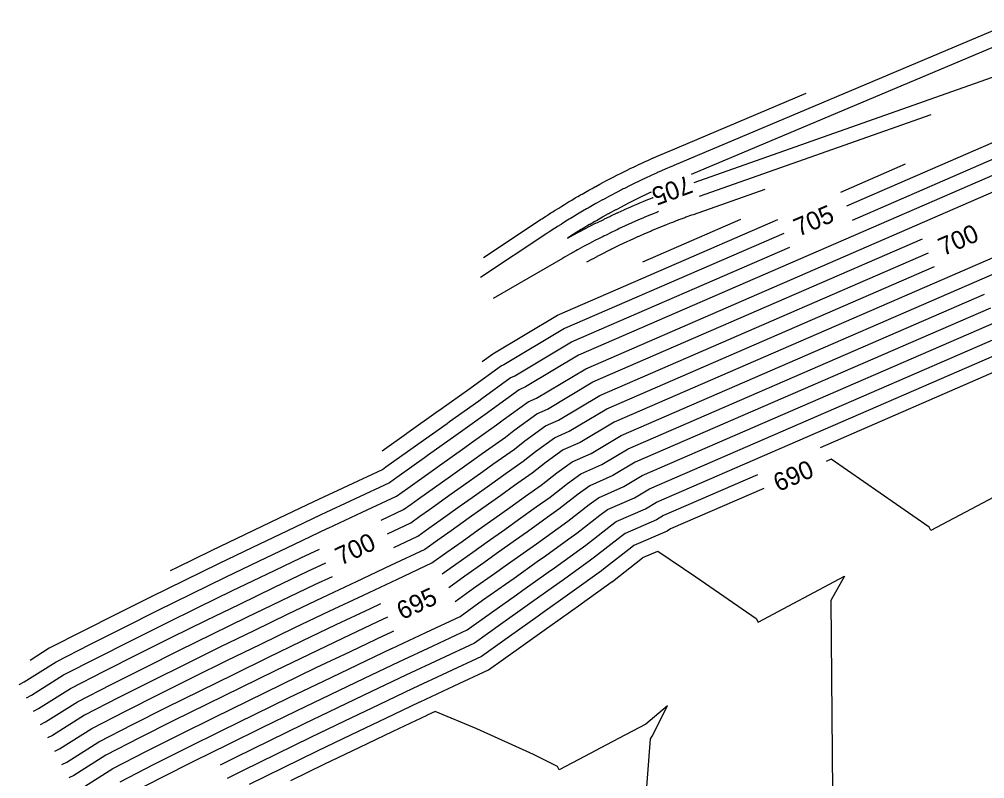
# Model space of a CAD drawing. Extents: x 1487507 to 1489130, y 497211 to 499439.
# Drawn here: x 1487812.8 to 1487940.5, y 498440 to 498540.5 of the extents above; entities that cross this region are included whole.
import ezdxf

# ---------------------------------------------------------------- set-up
doc = ezdxf.new("R2010")
doc.units = 0
for name, color, linetype in [('Prop CMT Ditch DDE', 7, 'Continuous'), ('Prop Drainage Ditch Flow Line', 7, 'Continuous'), ('Prop Drainage Structure Box Number Symbol CELL', 7, 'Continuous'), ('Prop Drainage Structure Pipe Outlet Channel Detail CELL', 7, 'Continuous')]:
    doc.layers.add(name, color=color, linetype=linetype)

msp = doc.modelspace()

# ---------------------------------------------------------------- linework, layer by layer
at = {"layer": 'Prop CMT Ditch DDE'}
for points in [[(1487945.21, 498540.46), (1487899.4, 498521.12), (1487899.22, 498521.05), (1487899.2, 498521.04), (1487899.1, 498520.99), (1487898.26, 498520.63), (1487898.16, 498520.59), (1487897.45, 498520.28), (1487897.44, 498520.27), (1487897.32, 498520.22), (1487897.2, 498520.16), (1487896.39, 498519.79), (1487895.65, 498519.45), (1487895.53, 498519.39), (1487895.46, 498519.36), (1487895.32, 498519.3), (1487894.53, 498518.92), (1487894.39, 498518.85), (1487893.62, 498518.47), (1487893.62, 498518.47), (1487892.86, 498518.09), (1487892.7, 498518.01), (1487892.54, 498517.92), (1487891.79, 498517.54), (1487891.73, 498517.51), (1487891.05, 498517.15), (1487890.89, 498517.06), (1487890.18, 498516.68), (1487889.99, 498516.58), (1487889.96, 498516.56), (1487889.86, 498516.51), (1487889.26, 498516.17), (1487889.09, 498516.08), (1487888.41, 498515.69), (1487888.2, 498515.58), (1487888.06, 498515.49), (1487888.02, 498515.47), (1487887.85, 498515.37), (1487887.32, 498515.06), (1487886.66, 498514.67), (1487886.44, 498514.54), (1487886.38, 498514.5), (1487886.19, 498514.39), (1487885.73, 498514.11), (1487885.57, 498514.01), (1487885.34, 498513.87), (1487884.7, 498513.47), (1487884.48, 498513.33), (1487884.4, 498513.28), (1487884, 498513.03), (1487883.84, 498512.93), (1487883.6, 498512.76), (1487882.99, 498512.37), (1487882.73, 498512.2), (1487882.62, 498512.13), (1487873.81, 498506.28)], [(1487874.23, 498508.96), (1487881.57, 498513.83), (1487881.77, 498513.96), (1487881.94, 498514.07), (1487882.41, 498514.38), (1487882.81, 498514.64), (1487883.12, 498514.84), (1487883.38, 498515), (1487883.55, 498515.11), (1487883.69, 498515.2), (1487884.17, 498515.49), (1487884.57, 498515.75), (1487884.92, 498515.95), (1487885.21, 498516.13), (1487885.33, 498516.2), (1487885.46, 498516.29), (1487885.89, 498516.54), (1487886.36, 498516.82), (1487886.71, 498517.02), (1487887.07, 498517.23), (1487887.16, 498517.28), (1487887.26, 498517.34), (1487887.73, 498517.61), (1487888.17, 498517.85), (1487888.59, 498518.09), (1487888.95, 498518.29), (1487889.02, 498518.33), (1487889.08, 498518.36), (1487889.6, 498518.64), (1487890, 498518.85), (1487890.5, 498519.12), (1487890.85, 498519.31), (1487890.92, 498519.34), (1487891.47, 498519.63), (1487891.85, 498519.82), (1487892.42, 498520.1), (1487892.78, 498520.29), (1487892.78, 498520.29), (1487893.13, 498520.46), (1487893.72, 498520.75), (1487894.06, 498520.91), (1487894.66, 498521.19), (1487894.73, 498521.23), (1487895.05, 498521.38), (1487895.6, 498521.64), (1487895.95, 498521.79), (1487896.56, 498522.07), (1487896.61, 498522.09), (1487896.69, 498522.13), (1487896.99, 498522.26), (1487897.51, 498522.49), (1487897.85, 498522.63), (1487898.47, 498522.9), (1487898.55, 498522.93), (1487898.68, 498522.99), (1487916.89, 498530.68)], [(1487933.36, 498527.82), (1487902.76, 498517.01)], [(1487923, 498513.9), (1487950.27, 498525.73)], [(1487951.2, 498523.97), (1487886.8, 498496), (1487879.8, 498491.81), (1487878.94, 498491.44), (1487875.42, 498488.88), (1487874.77, 498488.37), (1487871.18, 498485.83), (1487870.58, 498485.41), (1487866.97, 498482.84), (1487866.42, 498482.45), (1487862.77, 498479.83), (1487862.27, 498479.48), (1487861.79, 498479.13), (1487857.26, 498477), (1487852.73, 498474.88), (1487852.72, 498474.88), (1487848.2, 498472.74), (1487843.69, 498470.57), (1487839.18, 498468.4), (1487834.69, 498466.2), (1487830.2, 498463.99), (1487825.72, 498461.76), (1487821.26, 498459.52), (1487816.81, 498457.23), (1487814.29, 498455.63)], [(1487812.85, 498452.44), (1487813.51, 498452.78), (1487817.74, 498455.46), (1487822.19, 498457.75), (1487826.66, 498459.99), (1487831.14, 498462.22), (1487835.62, 498464.44), (1487840.12, 498466.63), (1487844.62, 498468.81), (1487849.14, 498470.97), (1487853.66, 498473.11), (1487853.67, 498473.12), (1487858.19, 498475.24), (1487862.72, 498477.36), (1487863.46, 498477.89), (1487864.2, 498478.42), (1487867.61, 498480.86), (1487868.41, 498481.42), (1487871.77, 498483.81), (1487872.61, 498484.42), (1487875.95, 498486.78), (1487876.84, 498487.47), (1487880.11, 498489.85), (1487881.24, 498490.35), (1487887.74, 498494.23), (1487952.14, 498522.2)], [(1487929.99, 498521.28), (1487921.41, 498517.55)], [(1487911.41, 498517.94), (1487901.93, 498514.59), (1487901.77, 498514.54), (1487901.74, 498514.53), (1487900.99, 498514.26), (1487900.84, 498514.2), (1487900.2, 498513.97), (1487900.07, 498513.92), (1487899.96, 498513.88), (1487899.94, 498513.87), (1487899.2, 498513.58), (1487899.05, 498513.53), (1487898.36, 498513.26), (1487898.22, 498513.2), (1487898.16, 498513.18), (1487897.41, 498512.88), (1487897.27, 498512.82), (1487896.53, 498512.51), (1487896.39, 498512.45), (1487895.64, 498512.13), (1487895.51, 498512.07), (1487894.76, 498511.74), (1487894.63, 498511.69), (1487894.57, 498511.66), (1487893.88, 498511.34), (1487893.76, 498511.29), (1487893.01, 498510.94), (1487892.89, 498510.89), (1487892.78, 498510.84), (1487892.77, 498510.83), (1487892.12, 498510.52), (1487892.03, 498510.47), (1487891.25, 498510.09), (1487891.16, 498510.05), (1487891, 498509.97), (1487890.98, 498509.96), (1487890.36, 498509.65), (1487890.31, 498509.62), (1487889.5, 498509.21), (1487889.45, 498509.18), (1487889.22, 498509.06), (1487889.21, 498509.05), (1487888.62, 498508.74), (1487888.61, 498508.73), (1487887.86, 498508.33)], [(1487955.88, 498515.13), (1487891.48, 498487.16), (1487887, 498484.48), (1487884.78, 498483.51), (1487882.51, 498481.86), (1487880.67, 498480.42), (1487878.34, 498478.78), (1487876.5, 498477.44), (1487874.15, 498475.77), (1487872.34, 498474.49), (1487869.95, 498472.78), (1487868.19, 498471.53), (1487866.47, 498470.29), (1487861.94, 498468.17), (1487857.41, 498466.04), (1487857.4, 498466.04), (1487852.88, 498463.9), (1487848.37, 498461.74), (1487843.86, 498459.56), (1487839.37, 498457.36), (1487834.88, 498455.15), (1487830.4, 498452.92), (1487825.93, 498450.68), (1487821.49, 498448.39), (1487817.25, 498445.71), (1487816.59, 498445.37)], [(1487897.36, 498515.01), (1487897.36, 498515.01), (1487897.22, 498514.95), (1487896.45, 498514.64), (1487896.3, 498514.58), (1487895.55, 498514.27), (1487895.55, 498514.27), (1487895.39, 498514.2), (1487894.65, 498513.88), (1487893.94, 498513.56), (1487893.76, 498513.48), (1487893.7, 498513.46), (1487893.53, 498513.38), (1487892.87, 498513.08), (1487892.18, 498512.76), (1487891.98, 498512.67), (1487891.88, 498512.62), (1487891.86, 498512.61), (1487891.69, 498512.53), (1487891.1, 498512.25), (1487890.43, 498511.92), (1487890.22, 498511.81), (1487890.17, 498511.79), (1487890.03, 498511.72), (1487889.52, 498511.46), (1487889.35, 498511.37), (1487889.12, 498511.26), (1487888.47, 498510.92), (1487888.41, 498510.89), (1487888.23, 498510.8), (1487887.78, 498510.56), (1487887.61, 498510.47), (1487887.37, 498510.34), (1487886.75, 498510), (1487886.66, 498509.95), (1487886.44, 498509.83), (1487886.05, 498509.62), (1487885.89, 498509.53), (1487885.63, 498509.38), (1487885.04, 498509.04), (1487884.92, 498508.98), (1487884.67, 498508.83), (1487875.52, 498503.52)], [(1487874.05, 498495.19), (1487875.44, 498496.19), (1487875.48, 498496.21), (1487883.99, 498501.31), (1487913.16, 498513.97)], [(1487895.3, 498508.39), (1487908.24, 498514.01)], [(1487817.53, 498443.6), (1487818.18, 498443.94), (1487822.42, 498446.62), (1487826.87, 498448.91), (1487831.34, 498451.16), (1487835.82, 498453.39), (1487840.3, 498455.6), (1487844.8, 498457.79), (1487849.3, 498459.97), (1487853.82, 498462.13), (1487858.34, 498464.27), (1487858.35, 498464.28), (1487862.87, 498466.4), (1487867.4, 498468.52), (1487869.37, 498469.94), (1487871.39, 498471.37), (1487873.52, 498472.9), (1487875.59, 498474.36), (1487877.69, 498475.85), (1487879.78, 498477.37), (1487881.85, 498478.83), (1487883.93, 498480.45), (1487885.95, 498481.92), (1487888.44, 498483.02), (1487892.42, 498485.4), (1487956.82, 498513.36)], [(1487860.68, 498474.19), (1487863.66, 498475.59), (1487864.64, 498476.3), (1487865.64, 498477.01), (1487868.79, 498479.27), (1487869.84, 498480.01), (1487872.95, 498482.22), (1487874.04, 498483.01), (1487877.13, 498485.19), (1487878.25, 498486.07), (1487881.27, 498488.26), (1487882.68, 498488.88), (1487888.67, 498492.47), (1487932.28, 498511.4)], [(1487832.83, 498467.52), (1487833.75, 498467.97), (1487838.25, 498470.17), (1487842.75, 498472.34), (1487847.27, 498474.5), (1487851.79, 498476.65), (1487851.8, 498476.65), (1487856.32, 498478.77), (1487860.85, 498480.9), (1487861.09, 498481.07), (1487861.33, 498481.24), (1487865.24, 498484.04), (1487865.53, 498484.25), (1487869.4, 498487), (1487869.74, 498487.25), (1487873.59, 498489.97), (1487874, 498490.28), (1487877.77, 498493.02), (1487878.36, 498493.28), (1487885.87, 498497.77), (1487914.75, 498510.31)], [(1487862.38, 498470.58), (1487865.53, 498472.06), (1487867.01, 498473.12), (1487868.51, 498474.19), (1487871.16, 498476.08), (1487872.72, 498477.19), (1487875.32, 498479.03), (1487876.91, 498480.19), (1487879.49, 498482.01), (1487881.09, 498483.26), (1487883.61, 498485.09), (1487885.56, 498485.95), (1487890.54, 498488.93), (1487933.87, 498507.75)], [(1487826.17, 498439.55), (1487830.61, 498441.84), (1487835.08, 498444.09), (1487839.56, 498446.32), (1487844.04, 498448.53), (1487848.54, 498450.72), (1487853.05, 498452.9), (1487857.56, 498455.06), (1487862.08, 498457.2), (1487862.09, 498457.21), (1487866.61, 498459.33), (1487871.15, 498461.45), (1487874.1, 498463.58), (1487877.13, 498465.73), (1487878.26, 498466.53), (1487881.34, 498468.71), (1487882.42, 498469.48), (1487885.51, 498471.72), (1487886.56, 498472.46), (1487889.6, 498474.84), (1487890.62, 498475.58), (1487894.2, 498477.15), (1487896.16, 498478.33), (1487960.56, 498506.29)], [(1487827.1, 498437.79), (1487831.55, 498440.07), (1487836.02, 498442.32), (1487840.49, 498444.55), (1487844.98, 498446.76), (1487849.48, 498448.95), (1487853.98, 498451.13), (1487858.49, 498453.29), (1487863.02, 498455.43), (1487863.03, 498455.44), (1487867.55, 498457.56), (1487872.08, 498459.69), (1487875.29, 498461.98), (1487878.57, 498464.32), (1487879.44, 498464.94), (1487882.77, 498467.3), (1487883.6, 498467.88), (1487886.95, 498470.31), (1487887.74, 498470.87), (1487891.01, 498473.43), (1487891.78, 498473.99), (1487895.64, 498475.69), (1487897.09, 498476.56), (1487961.49, 498504.52)], [(1487868.78, 498467.07), (1487870.55, 498468.35), (1487872.82, 498469.96), (1487874.71, 498471.31), (1487877.03, 498472.95), (1487878.87, 498474.26), (1487881.21, 498475.95), (1487883.03, 498477.23), (1487885.34, 498479.05), (1487887.11, 498480.33), (1487889.88, 498481.55), (1487893.35, 498483.63), (1487940.45, 498504.08)], [(1487870.49, 498463.42), (1487872.92, 498465.17), (1487875.69, 498467.14), (1487877.07, 498468.13), (1487879.9, 498470.12), (1487881.24, 498471.07), (1487884.08, 498473.13), (1487885.38, 498474.05), (1487888.18, 498476.24), (1487889.45, 498477.16), (1487892.76, 498478.62), (1487895.22, 498480.09), (1487942.04, 498500.42)], [(1487969.05, 498416.46), (1487968.8, 498443.48), (1487968.56, 498443.92), (1487979.99, 498449.97), (1487976.31, 498450.28), (1487966.14, 498457.34), (1487965.84, 498487.74), (1487967.65, 498490.96), (1487956.22, 498484.91), (1487955.99, 498485.35), (1487943.04, 498494.34), (1487918.73, 498483.78)], [(1487910.47, 498480.19), (1487898.03, 498474.79), (1487897.08, 498474.22), (1487892.95, 498472.41), (1487892.43, 498472.03), (1487888.92, 498469.28), (1487888.38, 498468.9), (1487884.79, 498466.29), (1487884.21, 498465.88), (1487880.62, 498463.35), (1487880, 498462.91), (1487876.47, 498460.39), (1487873.02, 498457.92), (1487868.49, 498455.79), (1487863.96, 498453.67), (1487863.95, 498453.67), (1487859.43, 498451.52), (1487854.92, 498449.36), (1487850.41, 498447.19), (1487845.92, 498444.99), (1487841.43, 498442.78), (1487839.41, 498441.77)], [(1487813.78, 498450.67), (1487814.44, 498451.01), (1487818.68, 498453.7), (1487823.13, 498455.98), (1487827.6, 498458.23), (1487832.07, 498460.46), (1487836.56, 498462.67), (1487841.05, 498464.86), (1487845.56, 498467.04), (1487850.07, 498469.2), (1487852.53, 498470.36)], [(1487843.3, 498439.24), (1487847.79, 498441.46), (1487852.28, 498443.65), (1487856.79, 498445.83), (1487861.3, 498447.99), (1487865.82, 498450.13), (1487865.83, 498450.14), (1487870.36, 498452.26), (1487874.89, 498454.38), (1487878.84, 498457.21), (1487882.88, 498460.09), (1487882.99, 498460.17), (1487887.08, 498463.06), (1487887.15, 498463.11), (1487891.25, 498466.07), (1487891.28, 498466.09), (1487895.27, 498469.22), (1487895.29, 498469.23), (1487897.26, 498470.1), (1487902.32, 498466.68), (1487910.28, 498461.16), (1487910.52, 498460.71), (1487921.94, 498466.76), (1487920.14, 498463.54), (1487920.43, 498433.15)], [(1487815.66, 498447.14), (1487816.31, 498447.48), (1487820.55, 498450.16), (1487825, 498452.45), (1487829.47, 498454.69), (1487833.94, 498456.92), (1487838.43, 498459.13), (1487842.93, 498461.33), (1487847.43, 498463.5), (1487851.94, 498465.66), (1487854.24, 498466.75)], [(1487818.46, 498441.84), (1487819.12, 498442.18), (1487823.36, 498444.86), (1487827.81, 498447.14), (1487832.27, 498449.39), (1487836.75, 498451.62), (1487841.24, 498453.83), (1487845.73, 498456.02), (1487850.24, 498458.2), (1487854.75, 498460.36), (1487859.27, 498462.51), (1487859.28, 498462.51), (1487860.67, 498463.16)], [(1487820.33, 498438.3), (1487820.99, 498438.64), (1487825.23, 498441.32), (1487829.68, 498443.61), (1487834.15, 498445.85), (1487838.62, 498448.08), (1487843.11, 498450.29), (1487847.6, 498452.49), (1487852.11, 498454.67), (1487856.62, 498456.83), (1487861.15, 498458.97), (1487861.16, 498458.97), (1487862.37, 498459.55)], [(1487895.65, 498436.55), (1487896.29, 498445.26), (1487896.51, 498445.6), (1487898.55, 498449.6), (1487895.67, 498447.19), (1487891.25, 498444.86), (1487886.83, 498442.52), (1487884.23, 498441.14), (1487884, 498441.58), (1487880.82, 498443.17), (1487873.36, 498446.59), (1487867.84, 498448.87), (1487866.77, 498448.37), (1487866.75, 498448.36), (1487862.24, 498446.22), (1487857.72, 498444.06), (1487853.22, 498441.88), (1487848.72, 498439.69)]]:
    msp.add_lwpolyline(points, dxfattribs=at)
at = {"layer": 'Prop Drainage Ditch Flow Line'}
for points in [[(1487945.93, 498538.6), (1487901.69, 498519.92)], [(1487902.07, 498518.88), (1487947.37, 498534.88)], [(1487956.69, 498530.69), (1487953.93, 498529.5), (1487949.33, 498527.5), (1487922.21, 498515.72)], [(1487896.4, 498517.6), (1487896.32, 498517.56), (1487896.26, 498517.53), (1487895.47, 498517.15), (1487895.35, 498517.1), (1487894.56, 498516.7), (1487894.45, 498516.65), (1487894.35, 498516.6), (1487893.56, 498516.2), (1487892.75, 498515.78), (1487892.66, 498515.74), (1487892.6, 498515.71), (1487892.53, 498515.67), (1487891.78, 498515.27), (1487891.71, 498515.23), (1487890.9, 498514.79), (1487890.78, 498514.73), (1487890.77, 498514.73), (1487890.72, 498514.7), (1487890.02, 498514.31), (1487889.97, 498514.28), (1487889.15, 498513.81), (1487889.14, 498513.81), (1487888.96, 498513.71), (1487888.31, 498513.33), (1487888.28, 498513.31), (1487888.25, 498513.29), (1487887.42, 498512.8), (1487887.18, 498512.65), (1487887.16, 498512.64), (1487886.57, 498512.28), (1487885.72, 498511.75), (1487885.72, 498511.75), (1487885.42, 498511.56), (1487885.32, 498511.5), (1487885.42, 498511.55), (1487885.73, 498511.72), (1487885.74, 498511.73), (1487886.61, 498512.2), (1487887.23, 498512.53), (1487887.25, 498512.54), (1487887.5, 498512.67), (1487887.52, 498512.68), (1487888.38, 498513.13), (1487889.05, 498513.47), (1487889.09, 498513.48), (1487889.09, 498513.49), (1487889.28, 498513.58), (1487890.12, 498513.99), (1487890.17, 498514.02), (1487890.22, 498514.04), (1487890.95, 498514.39), (1487891.06, 498514.44), (1487891.07, 498514.45), (1487891.91, 498514.84), (1487891.98, 498514.87), (1487892.04, 498514.9), (1487892.82, 498515.26), (1487892.89, 498515.28), (1487893.71, 498515.65), (1487893.8, 498515.69), (1487893.89, 498515.73), (1487894.71, 498516.08), (1487894.82, 498516.13), (1487895.63, 498516.47), (1487895.75, 498516.51), (1487896.56, 498516.84), (1487896.63, 498516.87), (1487896.67, 498516.89)], [(1487913.95, 498512.14), (1487884.93, 498499.54), (1487876.92, 498494.75), (1487876.6, 498494.61), (1487872.58, 498491.69), (1487872.42, 498491.56), (1487868.31, 498488.66), (1487868.22, 498488.59), (1487864.1, 498485.66), (1487864.06, 498485.63), (1487860.83, 498483.32)], [(1487861.53, 498472.39), (1487864.6, 498473.83), (1487865.82, 498474.71), (1487867.08, 498475.6), (1487869.97, 498477.68), (1487871.28, 498478.6), (1487874.13, 498480.63), (1487875.48, 498481.6), (1487878.31, 498483.6), (1487879.67, 498484.67), (1487882.44, 498486.68), (1487884.12, 498487.42), (1487889.61, 498490.7), (1487933.08, 498509.58)], [(1487941.24, 498502.25), (1487894.29, 498481.86), (1487891.32, 498480.08), (1487888.28, 498478.75), (1487886.76, 498477.64), (1487884.2, 498475.64), (1487882.64, 498474.54), (1487880.05, 498472.66), (1487878.46, 498471.53), (1487875.89, 498469.72), (1487874.26, 498468.55), (1487871.74, 498466.76), (1487869.64, 498465.25)], [(1487948.66, 498441.52), (1487943.28, 498445.25), (1487942.99, 498475.64), (1487944.8, 498478.86), (1487933.37, 498472.81), (1487933.14, 498473.25), (1487920.19, 498482.24), (1487919.52, 498481.95)], [(1487911.27, 498478.36), (1487898.97, 498473.02), (1487898.52, 498472.75), (1487894.12, 498470.82), (1487893.85, 498470.62), (1487890.1, 498467.69), (1487889.81, 498467.48), (1487885.97, 498464.7), (1487885.65, 498464.47), (1487881.81, 498461.76), (1487881.44, 498461.5), (1487877.65, 498458.8), (1487873.95, 498456.15), (1487869.42, 498454.03), (1487864.9, 498451.9), (1487864.89, 498451.9), (1487860.37, 498449.76), (1487855.85, 498447.6), (1487851.35, 498445.42), (1487846.85, 498443.22), (1487842.37, 498441.01), (1487840.31, 498439.99)], [(1487814.72, 498448.91), (1487815.38, 498449.25), (1487819.62, 498451.93), (1487824.06, 498454.21), (1487828.53, 498456.46), (1487833.01, 498458.69), (1487837.5, 498460.9), (1487841.99, 498463.09), (1487846.5, 498465.27), (1487851.01, 498467.43), (1487853.38, 498468.56)], [(1487861.52, 498461.35), (1487860.22, 498460.74), (1487860.21, 498460.74), (1487855.69, 498458.59), (1487851.17, 498456.43), (1487846.67, 498454.26), (1487842.17, 498452.06), (1487837.69, 498449.85), (1487833.21, 498447.62), (1487828.74, 498445.38), (1487824.29, 498443.09), (1487820.06, 498440.41), (1487819.4, 498440.07)]]:
    msp.add_lwpolyline(points, dxfattribs=at)

# ---------------------------------------------------------------- texts
at = {"layer": 'Prop Drainage Structure Box Number Symbol CELL'}
msp.add_text('705', height=2.4, rotation=200.2843, dxfattribs=at).set_placement((1487901.27, 498519.87))
at = {"layer": 'Prop Drainage Structure Pipe Outlet Channel Detail CELL'}
for s, rotation, p in [('705', 23.4722, (1487915.89, 498511.67)), ('700', 23.4722, (1487935.02, 498509.11)), ('690', 23.4722, (1487913.21, 498477.9)), ('700', 25.2692, (1487855.35, 498468.15)), ('695', 25.1673, (1487863.47, 498460.94))]:
    msp.add_text(s, height=2.4, rotation=rotation, dxfattribs=at).set_placement(p)

doc.saveas('drawing.dxf')
